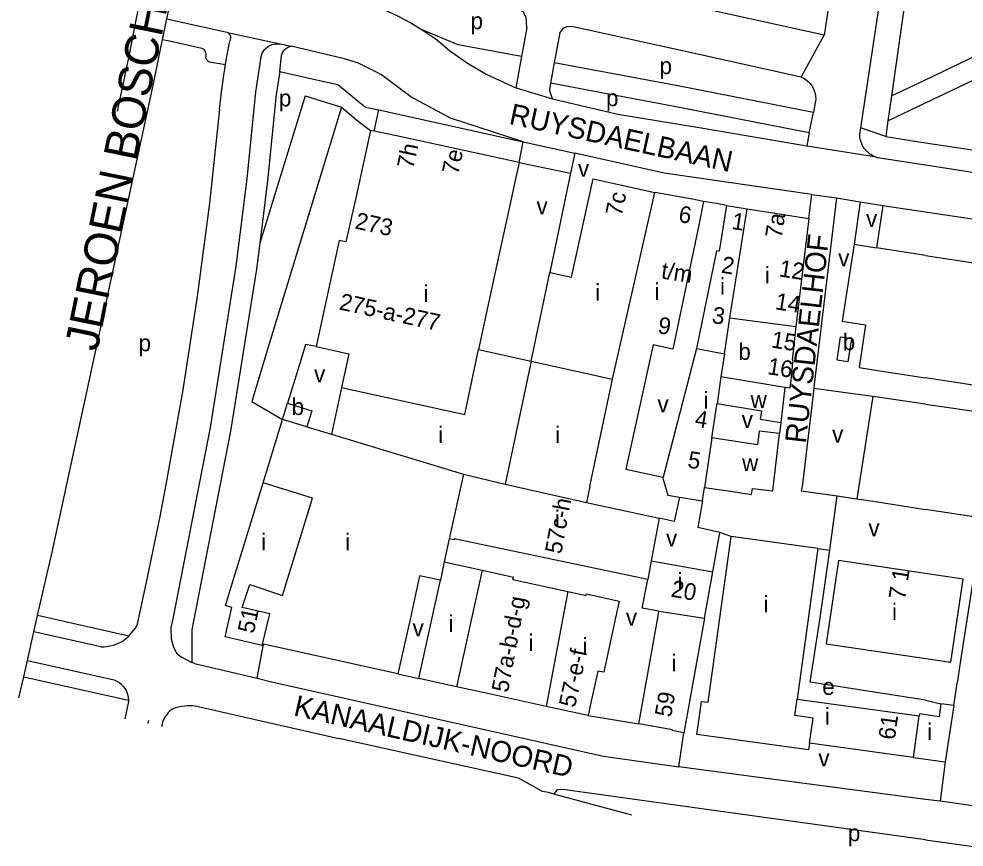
# Model space of a CAD drawing. Extents: x 163012 to 165277, y 382513 to 383987.
# Drawn here: x 163133.3 to 163359.2, y 382845.2 to 383043.1 of the extents above; entities that cross this region are included whole.
import ezdxf

# ---------------------------------------------------------------- set-up
doc = ezdxf.new("R2010")
doc.units = 0
for name, color, linetype in [('BLT_Basislijn', 7, 'Continuous'), ('BLT_Bebouwing', 7, 'Continuous'), ('BLT_Centroide', 7, 'Continuous'), ('BLT_Huisnummer', 7, 'Continuous'), ('BLT_Huisnummer_reeks', 7, 'Continuous'), ('BLT_Onderverdeling_panden', 7, 'Continuous'), ('BLT_Straatnaam', 7, 'Continuous'), ('BLT_Straatnaam_hoofdweg', 7, 'Continuous'), ('BLT_Vlakafsluiter', 7, 'Continuous')]:
    doc.layers.add(name, color=color, linetype=linetype)

msp = doc.modelspace()

# ---------------------------------------------------------------- linework, layer by layer
at = {"layer": 'BLT_Basislijn'}
for p, q in [((163340.61, 383057.98), (163334.42, 383017.07)), ((163346.19, 383055.07), (163341.87, 383024.69)), ((163350, 383028.58), (163396.61, 383050.87)), ((163168.71, 383043.11), (163169.9, 383048.84)), ((163350, 383023.04), (163398.77, 383046.36)), ((163167.7, 383038.21), (163168.71, 383043.11)), ((163254.68, 383041.1), (163253.43, 383034.12)), ((163262.59, 383039.86), (163261.29, 383032.65)), ((163253.43, 383034.12), (163252.09, 383026.68)), ((163261.29, 383032.65), (163260.4, 383027.73)), ((163341.87, 383024.69), (163350, 383028.58)), ((163260.4, 383027.73), (163260.12, 383026.15)), ((163260.85, 383024.03), (163260.12, 383026.15)), ((163341.87, 383024.69), (163341.02, 383018.74)), ((163218.26, 383016.28), (163219.35, 383021.36)), ((163323.65, 383023.07), (163323.19, 383020.77)), ((163341.02, 383018.74), (163350, 383023.04)), ((163322.22, 383015.86), (163323.19, 383020.77)), ((163340.49, 383014.99), (163334.42, 383017.07)), ((163252.88, 383008.8), (163253.87, 383013.74)), ((163253.87, 383013.74), (163266.17, 383011.01)), ((163350, 383013.53), (163425.61, 383001.92)), ((163266.17, 383011.01), (163265.18, 383006.27)), ((163339.03, 383009.89), (163350, 383008.2)), ((163252.88, 383008.8), (163265.18, 383006.27)), ((163265.18, 383006.27), (163260.2, 382982.49)), ((163322.07, 382995.43), (163322.79, 383001.15)), ((163322.79, 383001.15), (163328.68, 383000.36)), ((163328.68, 383000.36), (163334.4, 382999.38)), ((163334.4, 382999.38), (163339.8, 382998.53)), ((163339.8, 382998.53), (163338.3, 382988.41)), ((163200.7, 382961.52), (163197.55, 382951.25)), ((163337.36, 382952.9), (163323.28, 382954.8)), ((163315.4, 382946.68), (163315.1, 382944.03)), ((163328.87, 382929.11), (163333.58, 382928.43)), ((163296.67, 382927.91), (163295.62, 382921.6)), ((163300.82, 382920.37), (163295.62, 382921.6)), ((163299.13, 382910.95), (163300.82, 382920.37)), ((163137.82, 382900.53), (163141.26, 382915.64)), ((163324.27, 382916.52), (163327.11, 382916.14)), ((163136.93, 382896.63), (163137.82, 382900.53)), ((163159.61, 382895.63), (163137.82, 382900.53)), ((163135.38, 382889.8), (163136.93, 382896.63)), ((163152.96, 382893.02), (163136.93, 382896.63)), ((163190.29, 382885.52), (163191.73, 382893.27)), ((163134.49, 382885.9), (163135.38, 382889.8)), ((163135.38, 382889.8), (163156.08, 382885.15)), ((163175.33, 382889.08), (163174.69, 382889.32)), ((163175.33, 382889.08), (163190.29, 382885.52)), ((163133.35, 382880.87), (163134.49, 382885.9)), ((163134.49, 382885.9), (163159.55, 382880.27)), ((163223.9, 382886.58), (163228.9, 382885.46)), ((163356.75, 382879.03), (163357.51, 382884.38)), ((163159.55, 382879.97), (163158.64, 382875.8)), ((163176.16, 382878.77), (163209.83, 382871.11)), ((163350, 382880.27), (163353.68, 382879.45)), ((163269.34, 382876.6), (163281.47, 382874.65)), ((163164.32, 382875.44), (163164.16, 382874.7)), ((163167.69, 382875.06), (163167.47, 382874.04)), ((163291.05, 382864.39), (163292.26, 382872.51)), ((163354.66, 382865.53), (163353.47, 382856.13)), ((163261.16, 382857.86), (163259.92, 382858.19)), ((163279.82, 382852.8), (163261.16, 382857.86)), ((163353.47, 382856.13), (163350, 382856.59))]:
    msp.add_line(p, q, dxfattribs=at)
for points in [[(163336.35, 383108.85), (163325.76, 383039.25)], [(163156.91, 383021.07), (163159.66, 383034.21), (163167.7, 383075.17), (163170.26, 383091.62)], [(163254.68, 383041.1), (163254.56, 383043.48), (163253.84, 383044.83), (163252.55, 383045.56), (163233.19, 383049.97), (163228.83, 383050.95), (163221.36, 383051.95), (163219.66, 383051.91), (163218.77, 383051.75), (163218.13, 383051.54), (163217.55, 383051.02), (163217.03, 383050.49), (163216.66, 383050.02), (163216.29, 383049.38), (163216.08, 383048.75), (163216.13, 383047.96), (163216.76, 383047.17), (163217.24, 383046.7), (163217.9, 383046.28)], [(163217.9, 383046.28), (163220.86, 383045.24), (163223.78, 383043.85), (163227.01, 383042.2), (163229.74, 383040.54)], [(163325.76, 383039.25), (163300.01, 383044.87), (163297.38, 383045.46)], [(163168.71, 383043.11), (163170.41, 383042.73), (163182.74, 383040.03)], [(163320.26, 383029.2), (163295.48, 383034.7), (163269.48, 383040.44), (163265.4, 383041.31), (163264.24, 383041.24), (163263.33, 383040.86), (163262.59, 383039.86)], [(163167.79, 383038.64), (163167.89, 383039.11)], [(163182.74, 383040.03), (163183.05, 383039.91), (163183.16, 383039.85)], [(163183.16, 383039.85), (163183.26, 383039.8), (163183.44, 383039.67), (163183.63, 383039.5), (163183.76, 383039.31), (163183.88, 383039.13), (163183.93, 383038.88), (163183.92, 383038.6), (163183.86, 383038.19), (163183.77, 383037.77)], [(163253.43, 383034.12), (163238.33, 383036.95), (163229.74, 383040.54)], [(163229.74, 383040.54), (163233.04, 383038.26), (163236.28, 383035.59), (163240.28, 383032.67), (163245.04, 383029.88), (163252.09, 383026.68)], [(163141.26, 382915.64), (163165.51, 383027.63), (163167.7, 383038.21)], [(163167.7, 383038.21), (163169.33, 383037.85), (163177.03, 383036.16)], [(163182.74, 383032.23), (163182.99, 383033.73), (163183.77, 383037.77)], [(163191.1, 383033.5), (163191.48, 383034.93), (163192.05, 383035.81), (163192.97, 383036.59), (163193.78, 383036.99), (163194.95, 383037.14), (163195.75, 383037.15)], [(163195.75, 383037.15), (163196.08, 383037.07)], [(163196.08, 383037.07), (163196.66, 383037.02), (163197.23, 383036.87), (163198.4, 383036.58)], [(163177.03, 383036.16), (163177.34, 383035.96), (163177.51, 383035.82), (163177.69, 383035.59), (163177.86, 383035.34), (163177.95, 383035.09), (163178.03, 383034.77), (163178.03, 383034.53), (163178.02, 383034.36), (163177.98, 383034.11), (163177.95, 383033.92), (163177.97, 383033.81), (163178.03, 383033.64), (163178.18, 383033.42), (163178.42, 383033.15), (163178.66, 383032.93), (163178.92, 383032.82), (163179.15, 383032.77), (163179.81, 383032.67), (163182.74, 383032.23)], [(163195.7, 383030.52), (163196.08, 383034.38), (163196.6, 383035.59), (163197.64, 383036.39), (163198.4, 383036.58)], [(163253.87, 383013.74), (163236.47, 383019.42), (163226.97, 383024.49), (163219.97, 383029.72), (163218.32, 383030.64), (163214.48, 383032.51), (163211.15, 383033.54), (163198.4, 383036.58)], [(163191.1, 383033.5), (163189.88, 383025.65), (163187.8, 383004.93), (163185.21, 382984.01), (163179.02, 382945.47), (163170.1, 382899.72), (163169.69, 382897.66), (163169.72, 382894.99), (163170.21, 382893.23), (163171.04, 382891.49), (163172.16, 382890.66), (163174.69, 382889.32)], [(163323.19, 383020.77), (163290.83, 383027.11), (163261.29, 383032.65)], [(163181.3, 383021.53), (163181.75, 383025.61), (163182.31, 383029.68), (163182.74, 383032.23)], [(163195.7, 383030.52), (163194.84, 383025.02), (163192.77, 383004.38), (163190.92, 382989.48)], [(163195.7, 383030.52), (163203.06, 383028.91)], [(163203.06, 383028.91), (163209.58, 383027.4), (163216.15, 383022.06), (163219.35, 383021.36)], [(163320.26, 383029.2), (163320.86, 383028.92), (163321.43, 383028.57), (163321.94, 383028.15), (163322.4, 383027.67), (163322.81, 383027.14), (163323.14, 383026.57), (163323.41, 383025.96), (163323.6, 383025.32), (163323.71, 383024.67), (163323.74, 383024.01), (163323.69, 383023.34), (163323.65, 383023.07)], [(163252.09, 383026.68), (163252.38, 383026.55), (163260.85, 383024.03)], [(163322.22, 383015.86), (163289.89, 383022.2), (163260.4, 383027.73)], [(163201.78, 383024.76), (163190.92, 382989.48)], [(163201.78, 383024.76), (163210.45, 383022.04)], [(163260.85, 383024.03), (163276.48, 383020.33), (163296.39, 383017.12), (163321.61, 383012.75)], [(163181.3, 383021.53), (163178.87, 382999.11), (163175.93, 382976.74), (163172.49, 382954.45), (163168.55, 382932.25)], [(163210.45, 383022.04), (163193.11, 382965.45), (163189.04, 382951.7), (163196.37, 382947.4)], [(163210.45, 383022.04), (163214.43, 383018.64), (163217.34, 383016.48)], [(163219.35, 383021.36), (163253.87, 383013.74)], [(163341.02, 383018.74), (163340.49, 383014.99), (163350, 383013.53)], [(163334.42, 383017.07), (163334.19, 383015.53), (163334.24, 383014.85), (163334.37, 383014.18), (163334.57, 383013.54), (163334.85, 383012.91), (163335.2, 383012.33), (163335.62, 383011.79), (163336.1, 383011.31), (163336.63, 383010.88), (163337.21, 383010.52), (163337.82, 383010.23)], [(163322.22, 383015.86), (163321.61, 383012.75)], [(163322.79, 383001.15), (163287.55, 383006.21), (163266.17, 383011.01)], [(163337.82, 383010.23), (163338.47, 383010.01), (163339.03, 383009.89)], [(163350, 383008.2), (163367.79, 383005.47)], [(163302.42, 382998.53), (163300.01, 382999), (163296.91, 382999.51)], [(163328.68, 383000.36), (163323.39, 382955.74), (163323.28, 382954.8)], [(163334.4, 382999.38), (163332.93, 382989.24)], [(163339.8, 382998.53), (163411.36, 382987.86)], [(163190.92, 382989.48), (163190.16, 382983.3), (163183.94, 382944.6), (163175.01, 382898.74), (163174.69, 382897.2), (163174.69, 382889.32)], [(163204.37, 382964.8), (163201.87, 382965.32), (163200.7, 382961.52)], [(163323.28, 382954.8), (163320.51, 382931.32), (163320.25, 382930.34), (163328.87, 382929.11)], [(163168.55, 382932.25), (163166.99, 382924.17), (163165.36, 382916.11), (163163.66, 382908.06), (163161.5, 382898.18)], [(163327.11, 382916.14), (163327.21, 382916.81), (163328.87, 382929.11)], [(163363.57, 382923.8), (163359.9, 382900), (163358.25, 382889.32), (163357.51, 382884.38)], [(163303.53, 382919.38), (163300.82, 382920.37)], [(163350, 382880.27), (163322.39, 382884.59), (163324.78, 382900), (163327.11, 382916.14)], [(163159.61, 382895.63), (163160.27, 382896.37), (163161.21, 382897.47), (163161.41, 382897.9), (163161.5, 382898.18)], [(163152.96, 382893.02), (163153.27, 382893.01), (163153.7, 382893.06), (163155.11, 382893.25), (163155.98, 382893.47), (163156.96, 382893.81), (163157.99, 382894.34), (163158.8, 382894.92), (163159.61, 382895.63)], [(163190.29, 382885.52), (163193.4, 382884.78), (163273.07, 382866.89), (163291.05, 382864.39)], [(163156.08, 382885.15), (163156.9, 382884.77), (163157.22, 382884.56), (163157.59, 382884.28), (163157.98, 382883.91), (163158.35, 382883.49), (163158.65, 382883.08), (163158.94, 382882.59), (163159.19, 382881.98), (163159.36, 382881.38), (163159.49, 382880.84), (163159.55, 382880.27)], [(163159.55, 382880.27), (163159.55, 382879.97)], [(163176.16, 382878.77), (163175.47, 382878.88), (163174.92, 382878.93), (163174.23, 382878.96), (163173.6, 382878.94), (163172.96, 382878.9), (163172.31, 382878.82), (163171.46, 382878.66), (163170.82, 382878.49), (163170.34, 382878.33), (163169.92, 382878.09), (163169.43, 382877.71), (163169.04, 382877.31), (163168.76, 382876.98), (163168.44, 382876.55), (163168.17, 382876.13), (163167.96, 382875.73), (163167.69, 382875.06)], [(163259.92, 382858.19), (163258.5, 382858.5), (163252.74, 382861.69), (163209.83, 382871.11)], [(163350, 382856.59), (163300, 382863.15), (163291.05, 382864.39)], [(163350, 382846.93), (163300, 382853.88), (163263.35, 382858.92), (163261.85, 382858.9), (163261.16, 382857.86)], [(163385.07, 382851.6), (163384.62, 382851.67), (163353.47, 382856.13)], [(163350, 382846.93), (163362.62, 382845.18)]]:
    msp.add_lwpolyline(points, dxfattribs=at)
at = {"layer": 'BLT_Bebouwing'}
for p, q in [((163252.88, 383008.8), (163223.55, 383015.14)), ((163302.42, 382998.53), (163307.4, 382997.74)), ((163307.4, 382997.74), (163322.07, 382995.43)), ((163322.07, 382995.43), (163319.02, 382969.57)), ((163350, 382986.6), (163338.3, 382988.41)), ((163259.48, 382979.09), (163260.2, 382982.49)), ((163260.2, 382982.49), (163265.41, 382981.41)), ((163255.73, 382961.33), (163259.48, 382979.09)), ((163328.84, 382961.56), (163329.71, 382967.14)), ((163329.71, 382967.14), (163332.33, 382966.73)), ((163332.33, 382966.73), (163331.46, 382961.15)), ((163243.17, 382964.14), (163255.73, 382961.33)), ((163295.25, 382964.35), (163287.27, 382933.59)), ((163331.46, 382961.15), (163328.84, 382961.56)), ((163196.37, 382947.4), (163197.55, 382951.25)), ((163337.36, 382952.9), (163333.58, 382928.43)), ((163202.15, 382945.62), (163208.02, 382943.85)), ((163296.67, 382927.91), (163297.16, 382931.15)), ((163291.18, 382928.81), (163296.67, 382927.91)), ((163363.57, 382923.8), (163350, 382925.9)), ((163286.32, 382923.8), (163284.44, 382913.58)), ((163236.19, 382918.86), (163235, 382913.35)), ((163235, 382913.35), (163244.01, 382911.37)), ((163284.44, 382913.58), (163299.13, 382910.95)), ((163244.01, 382911.37), (163251.5, 382909.73)), ((163251.37, 382909.14), (163251.5, 382909.73)), ((163251.37, 382909.14), (163264.52, 382906.26)), ((163297.16, 382899.87), (163292.26, 382872.51)), ((163191.83, 382893.7), (163191.73, 382893.27)), ((163223.9, 382886.58), (163191.83, 382893.7)), ((163237.9, 382883.49), (163228.9, 382885.46)), ((163245.72, 382881.78), (163237.9, 382883.49)), ((163259.32, 382878.79), (163245.72, 382881.78)), ((163269.34, 382876.6), (163259.32, 382878.79)), ((163270.1, 382880.07), (163269.34, 382876.6)), ((163319.33, 382880.57), (163348.5, 382876.56)), ((163356.75, 382879.03), (163353.68, 382879.45)), ((163356.75, 382879.03), (163354.66, 382865.53)), ((163347.12, 382866.57), (163322.27, 382869.99)), ((163347.12, 382866.57), (163354.66, 382865.53))]:
    msp.add_line(p, q, dxfattribs=at)
for points in [[(163217.34, 383016.48), (163213.77, 382999.99), (163211.5, 382989.83)], [(163218.26, 383016.28), (163217.34, 383016.48)], [(163223.55, 383015.14), (163218.26, 383016.28)], [(163252.88, 383008.8), (163251.8, 383003.78), (163250.97, 383000), (163247.03, 382981.87), (163243.17, 382964.14)], [(163265.41, 382981.41), (163270.55, 383004.91), (163285.34, 383001.66)], [(163296.91, 382999.51), (163294.27, 383000), (163285.34, 383001.66)], [(163296.91, 382999.51), (163296, 382994.59), (163289.58, 382964.22)], [(163302.42, 382998.53), (163301.64, 382993.59), (163300.69, 382987.58), (163300.02, 382987.69), (163295.25, 382964.35)], [(163211.5, 382989.83), (163209.9, 382990.17), (163204.37, 382964.8)], [(163332.93, 382989.24), (163330.09, 382970.84), (163335.67, 382969.98), (163334.1, 382959.78), (163339.04, 382959.02), (163350, 382957.32)], [(163332.93, 382989.24), (163338.3, 382988.41)], [(163350, 382986.6), (163376.73, 382982.48), (163376.56, 382981.38), (163388.24, 382979.57), (163388.44, 382980.83), (163409.56, 382977.58)], [(163319.02, 382969.57), (163318.09, 382961.63), (163318.32, 382961.61), (163317.84, 382956.83), (163317.53, 382954.84), (163316.37, 382955.02)], [(163204.37, 382964.8), (163212.22, 382963.1), (163210.45, 382954.99)], [(163289.58, 382964.22), (163284.93, 382965.18), (163278.38, 382935.54), (163287.27, 382933.59)], [(163350, 382951.03), (163366.6, 382948.65), (163367.52, 382954.62), (163350, 382957.32)], [(163210.45, 382954.99), (163208.02, 382943.85)], [(163316.37, 382955.02), (163315.4, 382946.68)], [(163197.55, 382951.25), (163202.33, 382949.78), (163203.33, 382949.47), (163202.15, 382945.62)], [(163298.96, 382943), (163300, 382949.87), (163300.21, 382951.16)], [(163300.21, 382951.16), (163310.81, 382949.48), (163310.49, 382947.46), (163315.4, 382946.68)], [(163350, 382951.03), (163342.3, 382952.14), (163337.36, 382952.9)], [(163191.71, 382932.24), (163196.37, 382947.4)], [(163315.1, 382944.03), (163310.22, 382944.61), (163309.83, 382941.35), (163300, 382942.84), (163298.96, 382943)], [(163297.16, 382931.15), (163300, 382930.74), (163303.5, 382930.24), (163308.44, 382929.47), (163308.61, 382930.88), (163313.47, 382930.3), (163315.1, 382944.03)], [(163184.71, 382909.48), (163191.71, 382932.24)], [(163291.18, 382928.81), (163289.92, 382923.03), (163286.32, 382923.8)], [(163333.58, 382928.43), (163338.52, 382927.67), (163350, 382925.9)], [(163322.27, 382869.99), (163322.05, 382868.43), (163300, 382871.47), (163295.36, 382872.1), (163296.04, 382877.06), (163296.45, 382880.01), (163298.08, 382879.78), (163303.53, 382919.38)], [(163324.27, 382916.52), (163303.53, 382919.38)], [(163283.61, 382909.11), (163237.38, 382918.87), (163237.33, 382918.62), (163236.19, 382918.86)], [(163324.27, 382916.52), (163319.33, 382880.57)], [(163297.16, 382899.87), (163299.13, 382910.95)], [(163184.25, 382902.43), (163182.69, 382902.91), (163184.71, 382909.48)], [(163234.05, 382908.94), (163229.11, 382910.02), (163226.89, 382900), (163223.9, 382886.58)], [(163228.9, 382885.46), (163232.09, 382900), (163234.05, 382908.94)], [(163286.29, 382901.57), (163282.28, 382902.29), (163283.61, 382909.11)], [(163264.52, 382906.26), (163268.88, 382905.3), (163268.97, 382905.71), (163276.78, 382903.96)], [(163276.78, 382903.96), (163275.93, 382900), (163274.17, 382891.84), (163273.1, 382886.95), (163271.69, 382887.26), (163270.1, 382880.07)], [(163191.48, 382893.33), (163182.6, 382895.43), (163183.68, 382900), (163184.25, 382902.43)], [(163281.47, 382874.65), (163286.01, 382900), (163286.29, 382901.57)], [(163191.73, 382893.27), (163191.48, 382893.33)], [(163353.68, 382879.45), (163353.25, 382876.35), (163348.56, 382877), (163348.5, 382876.56)], [(163292.26, 382872.51), (163289.46, 382873.02), (163289.49, 382873.22), (163281.47, 382874.65)]]:
    msp.add_lwpolyline(points, dxfattribs=at)
msp.add_lwpolyline([(163329.19, 382913.65), (163326.24, 382893.78), (163356, 382889.35), (163358.96, 382909.23)], close=True, dxfattribs=at)
at = {"layer": 'BLT_Onderverdeling_panden'}
for p, q in [((163303.25, 382971.69), (163307.4, 382997.74)), ((163301.97, 382963.1), (163303.25, 382971.69)), ((163303.25, 382971.69), (163319.02, 382969.57)), ((163295.25, 382964.35), (163301.97, 382963.1)), ((163301.97, 382963.1), (163301.11, 382957.54)), ((163255.73, 382961.33), (163249.52, 382931.89)), ((163255.73, 382961.33), (163275.21, 382956.98)), ((163301.11, 382957.54), (163300.21, 382951.16)), ((163316.37, 382955.02), (163301.11, 382957.54)), ((163202.15, 382945.62), (163196.37, 382947.4)), ((163208.02, 382943.85), (163239.62, 382934.33)), ((163298.96, 382943), (163297.16, 382931.15)), ((163239.62, 382934.33), (163236.19, 382918.86)), ((163239.62, 382934.33), (163249.52, 382931.89)), ((163249.52, 382931.89), (163268.99, 382927.52)), ((163269.8, 382931.33), (163268.99, 382927.52)), ((163268.99, 382927.52), (163286.32, 382923.8)), ((163235, 382913.35), (163234.05, 382908.94)), ((163284.44, 382913.58), (163283.61, 382909.11)), ((163244.01, 382911.37), (163237.9, 382883.49)), ((163286.29, 382901.57), (163297.16, 382899.87)), ((163347.12, 382866.57), (163348.5, 382876.56))]:
    msp.add_line(p, q, dxfattribs=at)
for points in [[(163275.21, 382956.98), (163285.34, 383001.66)], [(163210.45, 382954.99), (163239.9, 382948.57), (163243.18, 382964.14)], [(163269.8, 382931.33), (163275.21, 382956.98)], [(163287.27, 382933.59), (163287.21, 382933.34), (163288.44, 382929.26), (163291.18, 382928.81)], [(163191.48, 382893.33), (163193.27, 382900.91), (163186.7, 382902.47), (163188.51, 382907.93), (163196.36, 382905.29), (163203.53, 382928.6), (163191.71, 382932.24)], [(163264.52, 382906.26), (163263.3, 382900), (163259.32, 382878.79)], [(163322.27, 382869.99), (163323.1, 382876.01), (163318.78, 382876.61), (163319.33, 382880.57)]]:
    msp.add_lwpolyline(points, dxfattribs=at)
at = {"layer": 'BLT_Vlakafsluiter'}
for p, q in [((163183.16, 383039.85), (163195.75, 383037.15)), ((163320.26, 383029.2), (163325.76, 383039.25)), ((163321.61, 383012.75), (163337.82, 383010.23))]:
    msp.add_line(p, q, dxfattribs=at)

# ---------------------------------------------------------------- texts
at = {"layer": 'BLT_Centroide'}
for s, p in [('p', (163241.27, 383040.66)), ('p', (163286.44, 383029.93)), ('p', (163195.48, 383022.21)), ('p', (163273.64, 383022.25)), ('v', (163266.94, 383005.39)), ('v', (163257.03, 382996.41)), ('v', (163335.78, 382993.4)), ('v', (163329.12, 382984.01)), ('i', (163311.59, 382979.88)), ('i', (163300.88, 382977.18)), ('i', (163230.05, 382975.47)), ('i', (163271.03, 382975.75)), ('i', (163285.24, 382975.95)), ('p', (163161.94, 382963.69)), ('b', (163330.21, 382963.94)), ('b', (163305.27, 382961.63)), ('i', (163296.94, 382949.98)), ('b', (163198.52, 382948.44)), ('v', (163285.94, 382949.09)), ('w', (163308.19, 382950.12)), ('v', (163306.07, 382945.34)), ('i', (163233.54, 382941.72)), ('i', (163261.5, 382941.72)), ('v', (163327.67, 382941.87)), ('w', (163306.16, 382935.03)), ('i', (163261.41, 382921.66)), ('v', (163336.35, 382919.48)), ('i', (163191.21, 382916.12)), ('i', (163211.3, 382916.12)), ('v', (163287.99, 382917.04)), ('i', (163290.76, 382906.72)), ('i', (163311.25, 382901.25)), ('i', (163341.98, 382899.42)), ('i', (163235.97, 382896.59)), ('v', (163278.39, 382898.12)), ('v', (163227.42, 382895.57)), ('i', (163255.12, 382892.02)), ('i', (163268.05, 382891.17)), ('i', (163289.31, 382887.17)), ('e', (163325.31, 382881.56)), ('i', (163325.9, 382874.44)), ('i', (163350.39, 382870.75)), ('v', (163324.39, 382864.48)), ('p', (163331.44, 382846.58))]:
    msp.add_text(s, height=4, dxfattribs=at).set_placement(p)
msp.add_text('v', height=4, rotation=359, dxfattribs=at).set_placement((163203.84, 382956.3))
at = {"layer": 'BLT_Huisnummer'}
for s, rotation, p in [('7c', 78.0754, (163277.37, 382995.8)), ('7 1', 81.2216, (163345.09, 382904.14)), ('20', 349.5533, (163288.98, 382905.09)), ('51', 78.255, (163189.49, 382896.06)), ('59', 79.8502, (163289.18, 382876.05)), ('61', 82.1713, (163342.65, 382870.67))]:
    msp.add_text(s, height=4, rotation=rotation, dxfattribs=at).set_placement(p)
at = {"layer": 'BLT_Huisnummer_reeks'}
for s, rotation, p in [('7h', 77.808, (163227.56, 383007.1)), ('7e', 77.808, (163238.29, 383005.71)), ('6', 351.0951, (163290.8, 382994.59)), ('273', 347.8076, (163213.45, 382993.05)), ('1', 351.0951, (163303.5, 382992.94)), ('7a', 81.0951, (163315.59, 382990.54)), ('t/m', 351.0951, (163286.65, 382981.12)), ('2', 350.709, (163301.02, 382982.49)), ('12', 351.0388, (163314.82, 382981.61)), ('275-a-277', 347.7158, (163209.68, 382973.71)), ('14', 351.0388, (163313.91, 382973.74)), ('3', 350.709, (163298.76, 382970.47)), ('9', 351.0951, (163285.87, 382968.01)), ('15', 351.0417, (163312.94, 382964.62)), ('16', 351.0388, (163312.05, 382958.25)), ('4', 350.709, (163294.67, 382945.74)), ('5', 350.709, (163292.96, 382935.92)), ('57c-h', 79.5354, (163262.94, 382915.08)), ('57a-b-d-g', 79.3572, (163250.19, 382881.96)), ('57-e-f', 77.8247, (163266.22, 382878.35))]:
    msp.add_text(s, height=4, rotation=rotation, dxfattribs=at).set_placement(p)
at = {"layer": 'BLT_Straatnaam'}
for s, rotation, p in [('RUYSDAELBAAN', 347.6548, (163250.25, 383018.07)), ('RUYSDAELHOF', 83.5753, (163321.37, 382941.51)), ('KANAALDIJK-NOORD', 347.3082, (163198.76, 382876.69))]:
    msp.add_text(s, height=5, rotation=rotation, dxfattribs=at).set_placement(p)
at = {"layer": 'BLT_Straatnaam_hoofdweg'}
msp.add_text('JEROEN BOSCHLAAN', height=7.9999, rotation=78.498, dxfattribs=at).set_placement((163152.1, 382963.46))

doc.saveas('drawing.dxf')
